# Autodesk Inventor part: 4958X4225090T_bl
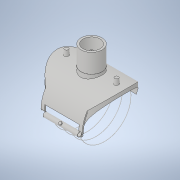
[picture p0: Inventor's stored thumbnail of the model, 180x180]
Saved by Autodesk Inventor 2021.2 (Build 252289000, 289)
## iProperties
Created: 2020-06
Part Number: 4958X4225090T_bl
Material: Generic
Description: Plasson Branch Saddle 225x90
Document SubType Name: Modeling
Designer: KIM
Density: 1 g/cm^3
Appearance: Default
Author: KIM
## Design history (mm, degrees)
derived "4958X4.ipt"
feature "Solid1::4958X4.ipt" dims "ScaleForDerivedMember" = 10
tag "TaggingFeature1"
body "Solid1"
other parameters: "d0" = 295 [user parameter], "d2" = 225 [user parameter], "d3" = 256.2 [user parameter], "d4" = 109 [user parameter], "d7" = 73 [user parameter], "d9" = 81 [user parameter], "d10" = 0.5 [user parameter], "d11" = 1 [user parameter], "d12" = 27.25 [user parameter], "d13" = 16 [user parameter], "d14" = 8 [user parameter], "d16" = 10 deg [user parameter], "d17" = 10 deg [user parameter], "d19" = 0 [user parameter], "d23" = 0 [user parameter], "d26" = 0 [user parameter], "d27" = 177 [user parameter], "d28" = 0 [user parameter], "d29" = 147.5 [user parameter], "d30" = 0 [user parameter], "d31" = 1 [user parameter], "d32" = 1 [user parameter], "d33" = 19.2 [user parameter], "d34" = 9.6 [user parameter], "d35" = 45 deg [user parameter], "d36" = 147.5 [user parameter], "d37" = 0 [user parameter], "d38" = 5 [user parameter], "d39" = 85 deg [user parameter], "d40" = 27.25 [user parameter], "d41" = 16 [user parameter], "d42" = 107.27273 [user parameter], "d49" = 3 [user parameter], "d50" = 6 [user parameter], "d51" = 5 [user parameter], "d54" = 0 [user parameter], "d57" = 35 deg [user parameter], "d60" = 18.4375 [user parameter], "d61" = 1 [user parameter], "d62" = 90 deg [user parameter], "d63" = 2 [user parameter], "d64" = 0 [user parameter], "d65" = 0 [user parameter], "d68" = 36.875 [user parameter], "d70" = 0.57711 [user parameter], "d71" = 10 deg [user parameter], "d73" = 5.46 [user parameter], "d" = 225 [user parameter], "B" = 277 [user parameter], "L" = 295 [user parameter], "LS" = 81 [user parameter], "H1" = 109 [user parameter], "Dt" = 16 [user parameter], "di" = 73 [user parameter], "d72" = 15.6 [user parameter]
